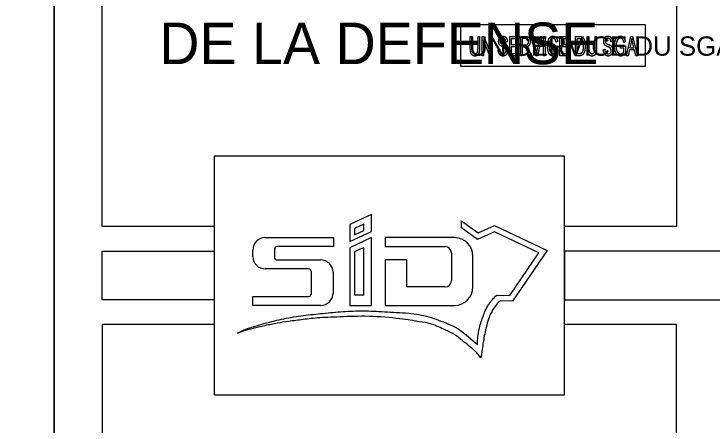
# Model space of a CAD drawing. Extents: x -21 to 21, y -29.7 to 0.
# Drawn here: x -0.42 to 6.85, y -16.68 to -12.39 of the extents above; entities that cross this region are included whole.
import ezdxf

# ---------------------------------------------------------------- set-up
doc = ezdxf.new("R2010")
doc.units = 0
doc.layers.add('Cartouches-Titres', color=7, linetype='Continuous')

msp = doc.modelspace()

# ---------------------------------------------------------------- linework, layer by layer
at = {"layer": 'Cartouches-Titres'}
for p, q in [((-0.0001, 0), (0, -29.7)), ((0, -29.7), (-0.0001, 0)), ((3.303, -14.4813), (3.0789, -14.5869)), ((3.303, -14.6586), (3.303, -14.4813)), ((3.0789, -14.5869), (3.0789, -14.7642)), ((3.223, -14.5835), (3.1269, -14.6288)), ((3.223, -14.648), (3.223, -14.5835)), ((4.2394, -14.6225), (4.2394, -14.5487)), ((3.0789, -14.7642), (3.303, -14.6586)), ((3.1269, -14.6288), (3.1269, -14.6932)), ((3.1269, -14.6932), (3.223, -14.648)), ((2.1958, -14.7231), (2.9061, -14.7231)), ((2.9061, -14.7231), (2.9061, -14.8166)), ((3.303, -14.7231), (3.0789, -14.8287)), ((3.303, -15.4292), (3.303, -14.7231)), ((4.1673, -14.7231), (3.447, -14.7231)), ((3.447, -14.7231), (3.447, -14.8166)), ((2.9061, -14.8166), (2.3238, -14.8166)), ((3.0789, -14.8287), (3.0789, -15.4292)), ((3.223, -14.8253), (3.1269, -14.8706)), ((3.223, -15.3196), (3.223, -14.8253)), ((3.447, -14.8166), (4.0713, -14.8166)), ((2.0677, -14.9198), (2.0677, -14.8521)), ((2.2918, -14.8488), (2.2918, -14.923)), ((3.1269, -14.8706), (3.1269, -15.3196)), ((4.1353, -14.8811), (4.1353, -15.1713)), ((2.3238, -14.9552), (2.7748, -14.9552)), ((3.6711, -14.9552), (3.447, -14.9552)), ((3.447, -14.9552), (3.447, -15.4292)), ((3.6711, -15.2357), (3.6711, -14.9552)), ((4.3594, -15.2357), (4.3594, -14.9166)), ((2.6467, -15.0487), (2.1958, -15.0487)), ((2.6787, -15.3035), (2.6787, -15.081)), ((2.9028, -15.0842), (2.9028, -15.3002)), ((4.0713, -15.2357), (3.6711, -15.2357)), ((2.0677, -15.4292), (2.0677, -15.3357)), ((2.0677, -15.3357), (2.6467, -15.3357)), ((3.1269, -15.3196), (3.223, -15.3196)), ((2.7748, -15.4292), (2.0677, -15.4292)), ((3.0789, -15.4292), (3.303, -15.4292)), ((3.447, -15.4292), (4.1673, -15.4292))]:
    msp.add_line(p, q, dxfattribs=at)
for points in [[(-20.9999, -29.7), (0, -29.7), (0, 0), (-20.9999, 0)], [(-0.0001, 0), (0, -29.7), (21, -29.7), (20.9999, 0)], [(0, -29.7), (20.9999, -29.7), (20.9999, 0), (0, 0)], [(4.2304, -12.9347), (6.1558, -12.9347), (6.1558, -12.5055), (4.2304, -12.5055)], [(1.6644, -16.3601), (5.3139, -16.3601), (5.3139, -13.8752), (1.6644, -13.8752)], [(0.4999, -14.8646), (1.6644, -14.8646), (1.6644, -15.3708), (0.4999, -15.3708)], [(20.5, -14.8646), (5.3139, -14.8646), (5.3139, -15.3708), (20.5, -15.3708)]]:
    msp.add_lwpolyline(points, close=True, dxfattribs=at)
for points in [[(1.6644, -14.6077), (0.4999, -14.6077), (0.4999, -0.5036), (6.4782, -0.5036), (6.4783, -14.6077), (5.3139, -14.6077)], [(4.3318, -12.7421), (4.3318, -12.6258), (4.348, -12.6258), (4.348, -12.7419)], [(4.4122, -12.7419), (4.4122, -12.6258), (4.4284, -12.6258), (4.4284, -12.7421)], [(4.471, -12.8272), (4.4554, -12.8272), (4.4554, -12.6258), (4.4721, -12.6258), (4.5367, -12.7839), (4.5367, -12.6258), (4.5522, -12.6258), (4.5522, -12.8272), (4.5356, -12.8272), (4.471, -12.6693), (4.471, -12.8272)], [(4.8344, -12.8272), (4.7427, -12.8272), (4.7427, -12.6258), (4.8315, -12.6258), (4.8315, -12.6496), (4.7589, -12.6496), (4.7589, -12.711), (4.8269, -12.711), (4.8269, -12.7348), (4.7589, -12.7348), (4.7589, -12.8034), (4.8344, -12.8034), (4.8344, -12.8272)], [(4.8731, -12.8272), (4.8569, -12.8272), (4.8569, -12.6258), (4.9114, -12.6258)], [(4.8731, -12.648), (4.8731, -12.7147), (4.9082, -12.7147)], [(4.9121, -12.648), (4.8731, -12.648)], [(5.0301, -12.8272), (5.0133, -12.8272), (4.9655, -12.6258), (4.9831, -12.6258), (5.0152, -12.7721)], [(5.0282, -12.7721), (5.0614, -12.6258), (5.078, -12.6258), (5.0301, -12.8272)], [(5.1119, -12.8272), (5.0957, -12.8272), (5.0957, -12.6258), (5.1119, -12.6258), (5.1119, -12.8272)], [(5.3565, -12.8272), (5.2647, -12.8272), (5.2647, -12.6258), (5.3536, -12.6258), (5.3536, -12.6496), (5.2809, -12.6496), (5.2809, -12.711), (5.3489, -12.711), (5.3489, -12.7348), (5.2809, -12.7348), (5.2809, -12.8034), (5.3565, -12.8034), (5.3565, -12.8272)], [(5.4708, -12.8272), (5.4264, -12.8272), (5.4264, -12.6258), (5.4689, -12.6258)], [(5.5508, -12.7421), (5.5508, -12.6258), (5.567, -12.6258), (5.567, -12.7419)], [(5.6312, -12.7419), (5.6312, -12.6258), (5.6474, -12.6258), (5.6474, -12.7421)], [(5.9748, -12.8272), (5.9575, -12.8272), (6.0047, -12.6258), (6.0224, -12.6258), (6.0726, -12.8272), (6.054, -12.8272), (6.0397, -12.7662), (5.9881, -12.7662), (5.9748, -12.8272)], [(4.7166, -12.6824), (4.701, -12.6842)], [(5.242, -12.6807), (5.226, -12.6869)], [(5.4426, -12.6496), (5.4426, -12.8034), (5.4689, -12.8034)], [(5.4685, -12.6496), (5.4426, -12.6496)], [(5.8115, -12.6824), (5.7959, -12.6842)], [(5.9453, -12.6821), (5.9307, -12.6886)], [(6.0064, -12.6854), (5.9928, -12.7444), (6.0346, -12.7444), (6.0219, -12.6887)], [(4.6223, -12.7623), (4.6377, -12.7601)], [(4.8919, -12.7377), (4.8731, -12.7377), (4.8731, -12.8272)], [(4.9438, -12.7724), (4.9653, -12.8272), (4.9448, -12.8272), (4.9284, -12.7853)], [(5.2278, -12.7566), (5.2441, -12.7633)], [(5.7173, -12.7623), (5.7327, -12.7601)], [(5.9313, -12.7482), (5.8952, -12.7482), (5.8952, -12.7244), (5.9473, -12.7242), (5.9473, -12.7991)], [(5.9313, -12.7856), (5.9313, -12.7482)], [(4.2394, -14.5487), (4.413, -14.673), (4.5847, -14.5962), (5.1338, -14.8569), (4.7728, -15.3865), (4.6465, -15.3818)], [(4.6119, -15.3216), (4.742, -15.3254), (5.0449, -14.8811), (4.584, -14.6623), (4.4062, -14.7419), (4.2394, -14.6225)], [(1.6644, -15.6276), (0.4999, -15.6276), (0.4999, -29.1964), (6.4783, -29.1964), (6.4783, -15.6276), (5.3139, -15.6276)]]:
    msp.add_lwpolyline(points, dxfattribs=at)
for centre, major_axis, start_param, end_param in [((2.1958, -14.8521), (0, -0.129), 3.141593, 4.712389), ((4.1673, -14.9166), (0, 0.1935), 4.712389, 6.283185), ((2.3238, -14.8488), (0, -0.0322), 3.141593, 4.712389), ((4.0713, -14.8811), (0, 0.0645), 4.712389, 6.283185), ((2.1958, -14.9198), (0, -0.129), 4.712389, 6.283185), ((2.3238, -14.923), (0, -0.0322), 4.712389, 6.283185), ((2.7748, -15.0842), (0, 0.129), 4.712389, 6.283185), ((2.6467, -15.081), (0, 0.0322), 4.712389, 6.283185), ((4.0713, -15.1713), (0, -0.0645), 0, 1.570796), ((4.1673, -15.2357), (0, 0.1935), 3.141593, 4.712389), ((2.6467, -15.3035), (0, -0.0322), 0, 1.570796), ((2.7748, -15.3002), (0, 0.129), 3.141593, 4.712389)]:
    msp.add_ellipse(centre, major_axis=major_axis, ratio=0.992906, start_param=start_param, end_param=end_param, dxfattribs=at)
for points, degree in [([(4.6271, -12.6777), (4.6271, -12.6532), (4.6388, -12.6377)], 2), ([(4.6388, -12.6377), (4.6506, -12.6222), (4.6706, -12.6222)], 2), ([(4.6711, -12.6457), (4.6572, -12.6457), (4.65, -12.654)], 2), ([(4.6706, -12.6222), (4.6843, -12.6222), (4.6946, -12.6295)], 2), ([(4.6922, -12.6551), (4.6847, -12.6457), (4.6711, -12.6457)], 2), ([(4.6946, -12.6295), (4.7048, -12.6367), (4.7105, -12.6504)], 2), ([(4.9114, -12.6258), (4.9285, -12.6258), (4.9366, -12.6314)], 2), ([(4.9319, -12.6567), (4.9252, -12.648), (4.9121, -12.648)], 2), ([(4.9366, -12.6314), (4.9448, -12.637), (4.95, -12.6501)], 2), ([(5.1431, -12.6687), (5.1508, -12.6457), (5.164, -12.6339)], 2), ([(5.164, -12.6339), (5.1772, -12.6222), (5.1935, -12.6222)], 2), ([(5.1931, -12.645), (5.1808, -12.645), (5.1718, -12.6535)], 2), ([(5.226, -12.6869), (5.2178, -12.645), (5.1931, -12.645)], 2), ([(5.1935, -12.6222), (5.2113, -12.6222), (5.2241, -12.637)], 2), ([(5.2241, -12.637), (5.2369, -12.6519), (5.242, -12.6807)], 2), ([(5.4689, -12.6258), (5.4846, -12.6258), (5.4928, -12.6295)], 2), ([(5.4928, -12.6295), (5.5036, -12.6343), (5.5114, -12.6471)], 2), ([(5.5114, -12.6471), (5.5193, -12.6598), (5.5237, -12.6793)], 2), ([(5.722, -12.6777), (5.722, -12.6532), (5.7338, -12.6377)], 2), ([(5.7338, -12.6377), (5.7455, -12.6222), (5.7655, -12.6222)], 2), ([(5.766, -12.6457), (5.7522, -12.6457), (5.7449, -12.654)], 2), ([(5.7655, -12.6222), (5.7792, -12.6222), (5.7895, -12.6295)], 2), ([(5.7872, -12.6551), (5.7796, -12.6457), (5.766, -12.6457)], 2), ([(5.7895, -12.6295), (5.7998, -12.6367), (5.8055, -12.6504)], 2), ([(5.8418, -12.6699), (5.8501, -12.6454), (5.8635, -12.6338)], 2), ([(5.8635, -12.6338), (5.8769, -12.6222), (5.8952, -12.6222)], 2), ([(5.8948, -12.645), (5.8814, -12.645), (5.8717, -12.6538)], 2), ([(5.9114, -12.6499), (5.904, -12.645), (5.8948, -12.645)], 2), ([(5.8952, -12.6222), (5.9087, -12.6222), (5.9188, -12.6289)], 2), ([(5.9188, -12.6289), (5.929, -12.6357), (5.9355, -12.6481)], 2), ([(5.9355, -12.6481), (5.9421, -12.6605), (5.9453, -12.6821)], 2), ([(6.0132, -12.6469), (6.0108, -12.6663), (6.0064, -12.6854)], 2), ([(6.0219, -12.6887), (6.0159, -12.663), (6.0132, -12.6469)], 2), ([(4.6312, -12.702), (4.6271, -12.6913), (4.6271, -12.6777)], 2), ([(4.6426, -12.7198), (4.6353, -12.7128), (4.6312, -12.702)], 2), ([(4.6674, -12.7338), (4.65, -12.7268), (4.6426, -12.7198)], 2), ([(4.65, -12.654), (4.6427, -12.6623), (4.6427, -12.6755)], 2), ([(4.6427, -12.6755), (4.6427, -12.6877), (4.648, -12.6944)], 2), ([(4.648, -12.6944), (4.6534, -12.7011), (4.672, -12.7081)], 2), ([(4.672, -12.7081), (4.6902, -12.7148), (4.6976, -12.7198)], 2), ([(4.701, -12.6842), (4.6997, -12.6646), (4.6922, -12.6551)], 2), ([(4.6976, -12.7198), (4.7088, -12.7276), (4.7146, -12.7401)], 2), ([(4.7105, -12.6504), (4.7162, -12.664), (4.7166, -12.6824)], 2), ([(4.9082, -12.7147), (4.9197, -12.7147), (4.9256, -12.711)], 2), ([(4.9464, -12.7175), (4.9376, -12.7316), (4.9207, -12.7355)], 2), ([(4.9256, -12.711), (4.9316, -12.7073), (4.9351, -12.6993)], 2), ([(4.9385, -12.6807), (4.9385, -12.6655), (4.9319, -12.6567)], 2), ([(4.9351, -12.6993), (4.9385, -12.6913), (4.9385, -12.6807)], 2), ([(4.9552, -12.6806), (4.9552, -12.7034), (4.9464, -12.7175)], 2), ([(4.95, -12.6501), (4.9552, -12.6633), (4.9552, -12.6806)], 2), ([(5.1353, -12.725), (5.1353, -12.6917), (5.1431, -12.6687)], 2), ([(5.1574, -12.6798), (5.152, -12.6977), (5.152, -12.725)], 2), ([(5.1718, -12.6535), (5.1628, -12.6619), (5.1574, -12.6798)], 2), ([(5.4893, -12.6535), (5.4827, -12.6496), (5.4685, -12.6496)], 2), ([(5.5052, -12.677), (5.499, -12.6594), (5.4893, -12.6535)], 2), ([(5.5114, -12.7251), (5.5114, -12.6945), (5.5052, -12.677)], 2), ([(5.5237, -12.6793), (5.5281, -12.6987), (5.5281, -12.7254)], 2), ([(5.7261, -12.702), (5.722, -12.6913), (5.722, -12.6777)], 2), ([(5.7376, -12.7198), (5.7302, -12.7128), (5.7261, -12.702)], 2), ([(5.7623, -12.7338), (5.7449, -12.7268), (5.7376, -12.7198)], 2), ([(5.7449, -12.654), (5.7377, -12.6623), (5.7377, -12.6755)], 2), ([(5.7377, -12.6755), (5.7377, -12.6877), (5.743, -12.6944)], 2), ([(5.743, -12.6944), (5.7483, -12.7011), (5.7669, -12.7081)], 2), ([(5.7669, -12.7081), (5.7851, -12.7148), (5.7925, -12.7198)], 2), ([(5.7959, -12.6842), (5.7947, -12.6646), (5.7872, -12.6551)], 2), ([(5.7925, -12.7198), (5.8038, -12.7276), (5.8095, -12.7401)], 2), ([(5.8055, -12.6504), (5.8111, -12.664), (5.8115, -12.6824)], 2), ([(5.8336, -12.7274), (5.8336, -12.6944), (5.8418, -12.6699)], 2), ([(5.8561, -12.6809), (5.8502, -12.6993), (5.8502, -12.7258)], 2), ([(5.8717, -12.6538), (5.862, -12.6625), (5.8561, -12.6809)], 2), ([(5.9233, -12.6631), (5.9188, -12.6547), (5.9114, -12.6499)], 2), ([(5.9307, -12.6886), (5.9278, -12.6716), (5.9233, -12.6631)], 2), ([(4.3439, -12.8111), (4.3318, -12.7916), (4.3318, -12.7421)], 2), ([(4.348, -12.7419), (4.348, -12.7693), (4.3512, -12.7815)], 2), ([(4.3512, -12.7815), (4.3544, -12.7937), (4.3616, -12.8001)], 2), ([(4.3792, -12.8065), (4.3965, -12.8065), (4.4044, -12.7933)], 2), ([(4.4044, -12.7933), (4.4122, -12.7801), (4.4122, -12.7419)], 2), ([(4.4242, -12.7901), (4.4199, -12.8089), (4.4088, -12.8198)], 2), ([(4.4284, -12.7421), (4.4284, -12.7714), (4.4242, -12.7901)], 2), ([(4.6364, -12.8122), (4.6228, -12.7938), (4.6223, -12.7623)], 2), ([(4.6377, -12.7601), (4.639, -12.7767), (4.6433, -12.786)], 2), ([(4.6433, -12.786), (4.6477, -12.7953), (4.6557, -12.8009)], 2), ([(4.6928, -12.7459), (4.6869, -12.7416), (4.6674, -12.7338)], 2), ([(4.7016, -12.7568), (4.6987, -12.7501), (4.6928, -12.7459)], 2), ([(4.6965, -12.797), (4.7046, -12.7875), (4.7046, -12.7723)], 2), ([(4.7046, -12.7723), (4.7046, -12.7634), (4.7016, -12.7568)], 2), ([(4.7203, -12.7701), (4.7203, -12.7874), (4.7143, -12.8016)], 2), ([(4.7146, -12.7401), (4.7203, -12.7527), (4.7203, -12.7701)], 2), ([(4.9046, -12.7407), (4.9001, -12.7377), (4.8919, -12.7377)], 2), ([(4.914, -12.7522), (4.9092, -12.7437), (4.9046, -12.7407)], 2), ([(4.9284, -12.7853), (4.9189, -12.7608), (4.914, -12.7522)], 2), ([(4.9207, -12.7355), (4.9275, -12.741), (4.931, -12.7467)], 2), ([(4.931, -12.7467), (4.9383, -12.7582), (4.9438, -12.7724)], 2), ([(5.0152, -12.7721), (5.0189, -12.7891), (5.0216, -12.8051)], 2), ([(5.0216, -12.8051), (5.0245, -12.7884), (5.0282, -12.7721)], 2), ([(5.1431, -12.7835), (5.1353, -12.7587), (5.1353, -12.725)], 2), ([(5.1629, -12.8194), (5.1508, -12.8082), (5.1431, -12.7835)], 2), ([(5.152, -12.725), (5.152, -12.7664), (5.1629, -12.7871)], 2), ([(5.1629, -12.7871), (5.1737, -12.8077), (5.1918, -12.8077)], 2), ([(5.2148, -12.7951), (5.2245, -12.7824), (5.2278, -12.7566)], 2), ([(5.2441, -12.7633), (5.2387, -12.7972), (5.2251, -12.8139)], 2), ([(5.493, -12.7965), (5.5012, -12.7895), (5.5056, -12.7741)], 2), ([(5.5206, -12.7834), (5.5132, -12.8073), (5.5015, -12.8172)], 2), ([(5.5056, -12.7741), (5.5114, -12.7537), (5.5114, -12.7251)], 2), ([(5.5281, -12.7254), (5.5281, -12.7596), (5.5206, -12.7834)], 2), ([(5.5629, -12.8111), (5.5508, -12.7916), (5.5508, -12.7421)], 2), ([(5.567, -12.7419), (5.567, -12.7693), (5.5702, -12.7815)], 2), ([(5.5702, -12.7815), (5.5734, -12.7937), (5.5806, -12.8001)], 2), ([(5.5981, -12.8065), (5.6155, -12.8065), (5.6234, -12.7933)], 2), ([(5.6234, -12.7933), (5.6312, -12.7801), (5.6312, -12.7419)], 2), ([(5.6432, -12.7901), (5.6389, -12.8089), (5.6278, -12.8198)], 2), ([(5.6474, -12.7421), (5.6474, -12.7714), (5.6432, -12.7901)], 2), ([(5.7313, -12.8122), (5.7178, -12.7938), (5.7173, -12.7623)], 2), ([(5.7327, -12.7601), (5.7339, -12.7767), (5.7382, -12.786)], 2), ([(5.7382, -12.786), (5.7426, -12.7953), (5.7507, -12.8009)], 2), ([(5.7878, -12.7459), (5.7819, -12.7416), (5.7623, -12.7338)], 2), ([(5.7966, -12.7568), (5.7937, -12.7501), (5.7878, -12.7459)], 2), ([(5.7915, -12.797), (5.7995, -12.7875), (5.7995, -12.7723)], 2), ([(5.7995, -12.7723), (5.7995, -12.7634), (5.7966, -12.7568)], 2), ([(5.8153, -12.7701), (5.8153, -12.7874), (5.8092, -12.8016)], 2), ([(5.8095, -12.7401), (5.8153, -12.7527), (5.8153, -12.7701)], 2), ([(5.8418, -12.7832), (5.8336, -12.7599), (5.8336, -12.7274)], 2), ([(5.8641, -12.8185), (5.85, -12.8064), (5.8418, -12.7832)], 2), ([(5.8502, -12.7258), (5.8502, -12.7662), (5.8628, -12.7864)], 2), ([(5.8628, -12.7864), (5.8754, -12.8065), (5.8956, -12.8065)], 2), ([(5.9153, -12.8003), (5.9254, -12.7941), (5.9313, -12.7856)], 2), ([(4.3803, -12.8306), (4.356, -12.8306), (4.3439, -12.8111)], 2), ([(4.3616, -12.8001), (4.3688, -12.8065), (4.3792, -12.8065)], 2), ([(4.4088, -12.8198), (4.3976, -12.8306), (4.3803, -12.8306)], 2), ([(4.6728, -12.8306), (4.65, -12.8306), (4.6364, -12.8122)], 2), ([(4.6557, -12.8009), (4.6638, -12.8065), (4.674, -12.8065)], 2), ([(4.6978, -12.8232), (4.6874, -12.8306), (4.6728, -12.8306)], 2), ([(4.674, -12.8065), (4.6885, -12.8065), (4.6965, -12.797)], 2), ([(4.7143, -12.8016), (4.7082, -12.8158), (4.6978, -12.8232)], 2), ([(5.1921, -12.8306), (5.175, -12.8306), (5.1629, -12.8194)], 2), ([(5.1918, -12.8077), (5.2051, -12.8077), (5.2148, -12.7951)], 2), ([(5.2251, -12.8139), (5.2116, -12.8306), (5.1921, -12.8306)], 2), ([(5.4689, -12.8034), (5.4848, -12.8034), (5.493, -12.7965)], 2), ([(5.5015, -12.8172), (5.4897, -12.8272), (5.4708, -12.8272)], 2), ([(5.5993, -12.8306), (5.575, -12.8306), (5.5629, -12.8111)], 2), ([(5.5806, -12.8001), (5.5878, -12.8065), (5.5981, -12.8065)], 2), ([(5.6278, -12.8198), (5.6166, -12.8306), (5.5993, -12.8306)], 2), ([(5.7677, -12.8306), (5.7449, -12.8306), (5.7313, -12.8122)], 2), ([(5.7507, -12.8009), (5.7588, -12.8065), (5.7689, -12.8065)], 2), ([(5.7928, -12.8232), (5.7824, -12.8306), (5.7677, -12.8306)], 2), ([(5.7689, -12.8065), (5.7834, -12.8065), (5.7915, -12.797)], 2), ([(5.8092, -12.8016), (5.8032, -12.8158), (5.7928, -12.8232)], 2), ([(5.8963, -12.8306), (5.8783, -12.8306), (5.8641, -12.8185)], 2), ([(5.8956, -12.8065), (5.9052, -12.8065), (5.9153, -12.8003)], 2), ([(5.9225, -12.8227), (5.9098, -12.8306), (5.8963, -12.8306)], 2), ([(5.9473, -12.7991), (5.9353, -12.8148), (5.9225, -12.8227)], 2), ([(4.4062, -15.8382), (4.406, -15.8021), (4.4105, -15.7484), (4.421, -15.6973), (4.4346, -15.6313), (4.4552, -15.5654), (4.4803, -15.5028), (4.4962, -15.4629), (4.5188, -15.4247), (4.5439, -15.3901), (4.5627, -15.3642), (4.5863, -15.3405), (4.6119, -15.3216)], 3), ([(4.6465, -15.3818), (4.6295, -15.3918), (4.6139, -15.4063), (4.6026, -15.4227), (4.5751, -15.4627), (4.5466, -15.505), (4.5302, -15.5509), (4.5013, -15.6317), (4.4798, -15.7346), (4.4684, -15.8017), (4.4593, -15.8608), (4.451, -15.9273), (4.4425, -15.9765)], 3), ([(1.9081, -15.7172), (1.9958, -15.6704), (2.201, -15.6117), (2.3884, -15.5662), (2.5939, -15.5319), (2.7986, -15.5121), (3.0067, -15.4918), (3.2177, -15.4825), (3.4278, -15.4948), (3.699, -15.5073), (3.898, -15.5385), (4.1056, -15.6256), (4.2188, -15.6657), (4.4062, -15.8382)], 3), ([(4.4425, -15.9765), (4.405, -15.9275), (4.3676, -15.8898), (4.327, -15.8581), (4.2497, -15.7978), (4.172, -15.7302), (4.0827, -15.6922), (3.9179, -15.612), (3.8049, -15.6016), (3.6625, -15.5752), (3.315, -15.536), (2.9988, -15.5482), (2.7525, -15.5567), (2.5935, -15.5757), (2.4351, -15.5975), (2.3266, -15.6125), (2.1905, -15.6401), (2.0666, -15.6691), (2.0014, -15.6869), (1.9081, -15.7172)], 3)]:
    msp.add_open_spline(points, degree=degree, dxfattribs=at)

# ---------------------------------------------------------------- texts
for s, height, p in [('DE LA DEFENSE', 0.433173, (1.0938, -12.9149)), ('UN SERVICE DU SGA ', 0.201429, (4.3186, -12.8272))]:
    msp.add_text(s, height=height, rotation=360, dxfattribs=at).set_placement(p)

doc.saveas('drawing.dxf')
